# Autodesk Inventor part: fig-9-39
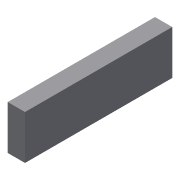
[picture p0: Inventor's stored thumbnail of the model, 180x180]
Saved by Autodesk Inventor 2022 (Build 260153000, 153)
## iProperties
Created: 2013-03
Part Number: fig-9-39
Material: Generic
Document SubType Name: Modeling
Designer: CADCIM
Density: 1 g/cm^3
Appearance: Default
Author: CADCIM
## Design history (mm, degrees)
sketch "Sketch1"
  geometry: L1 (-11.87, 2.655)-(7.31, 2.655); L2 (7.31, 2.655)-(7.31, -3.093); L3 (7.31, -3.093)-(-11.87, -3.093); L4 (-11.87, -3.093)-(-11.87, 2.655); 1 further point
  constraints: 8 end point, 2 parallel, 1 horizontal, 1 perpendicular
extrude "Extrusion1" new body sketch "Sketch1" distance "d0" = 2.25; taper "d1" = 0 deg
body "Solid1"
